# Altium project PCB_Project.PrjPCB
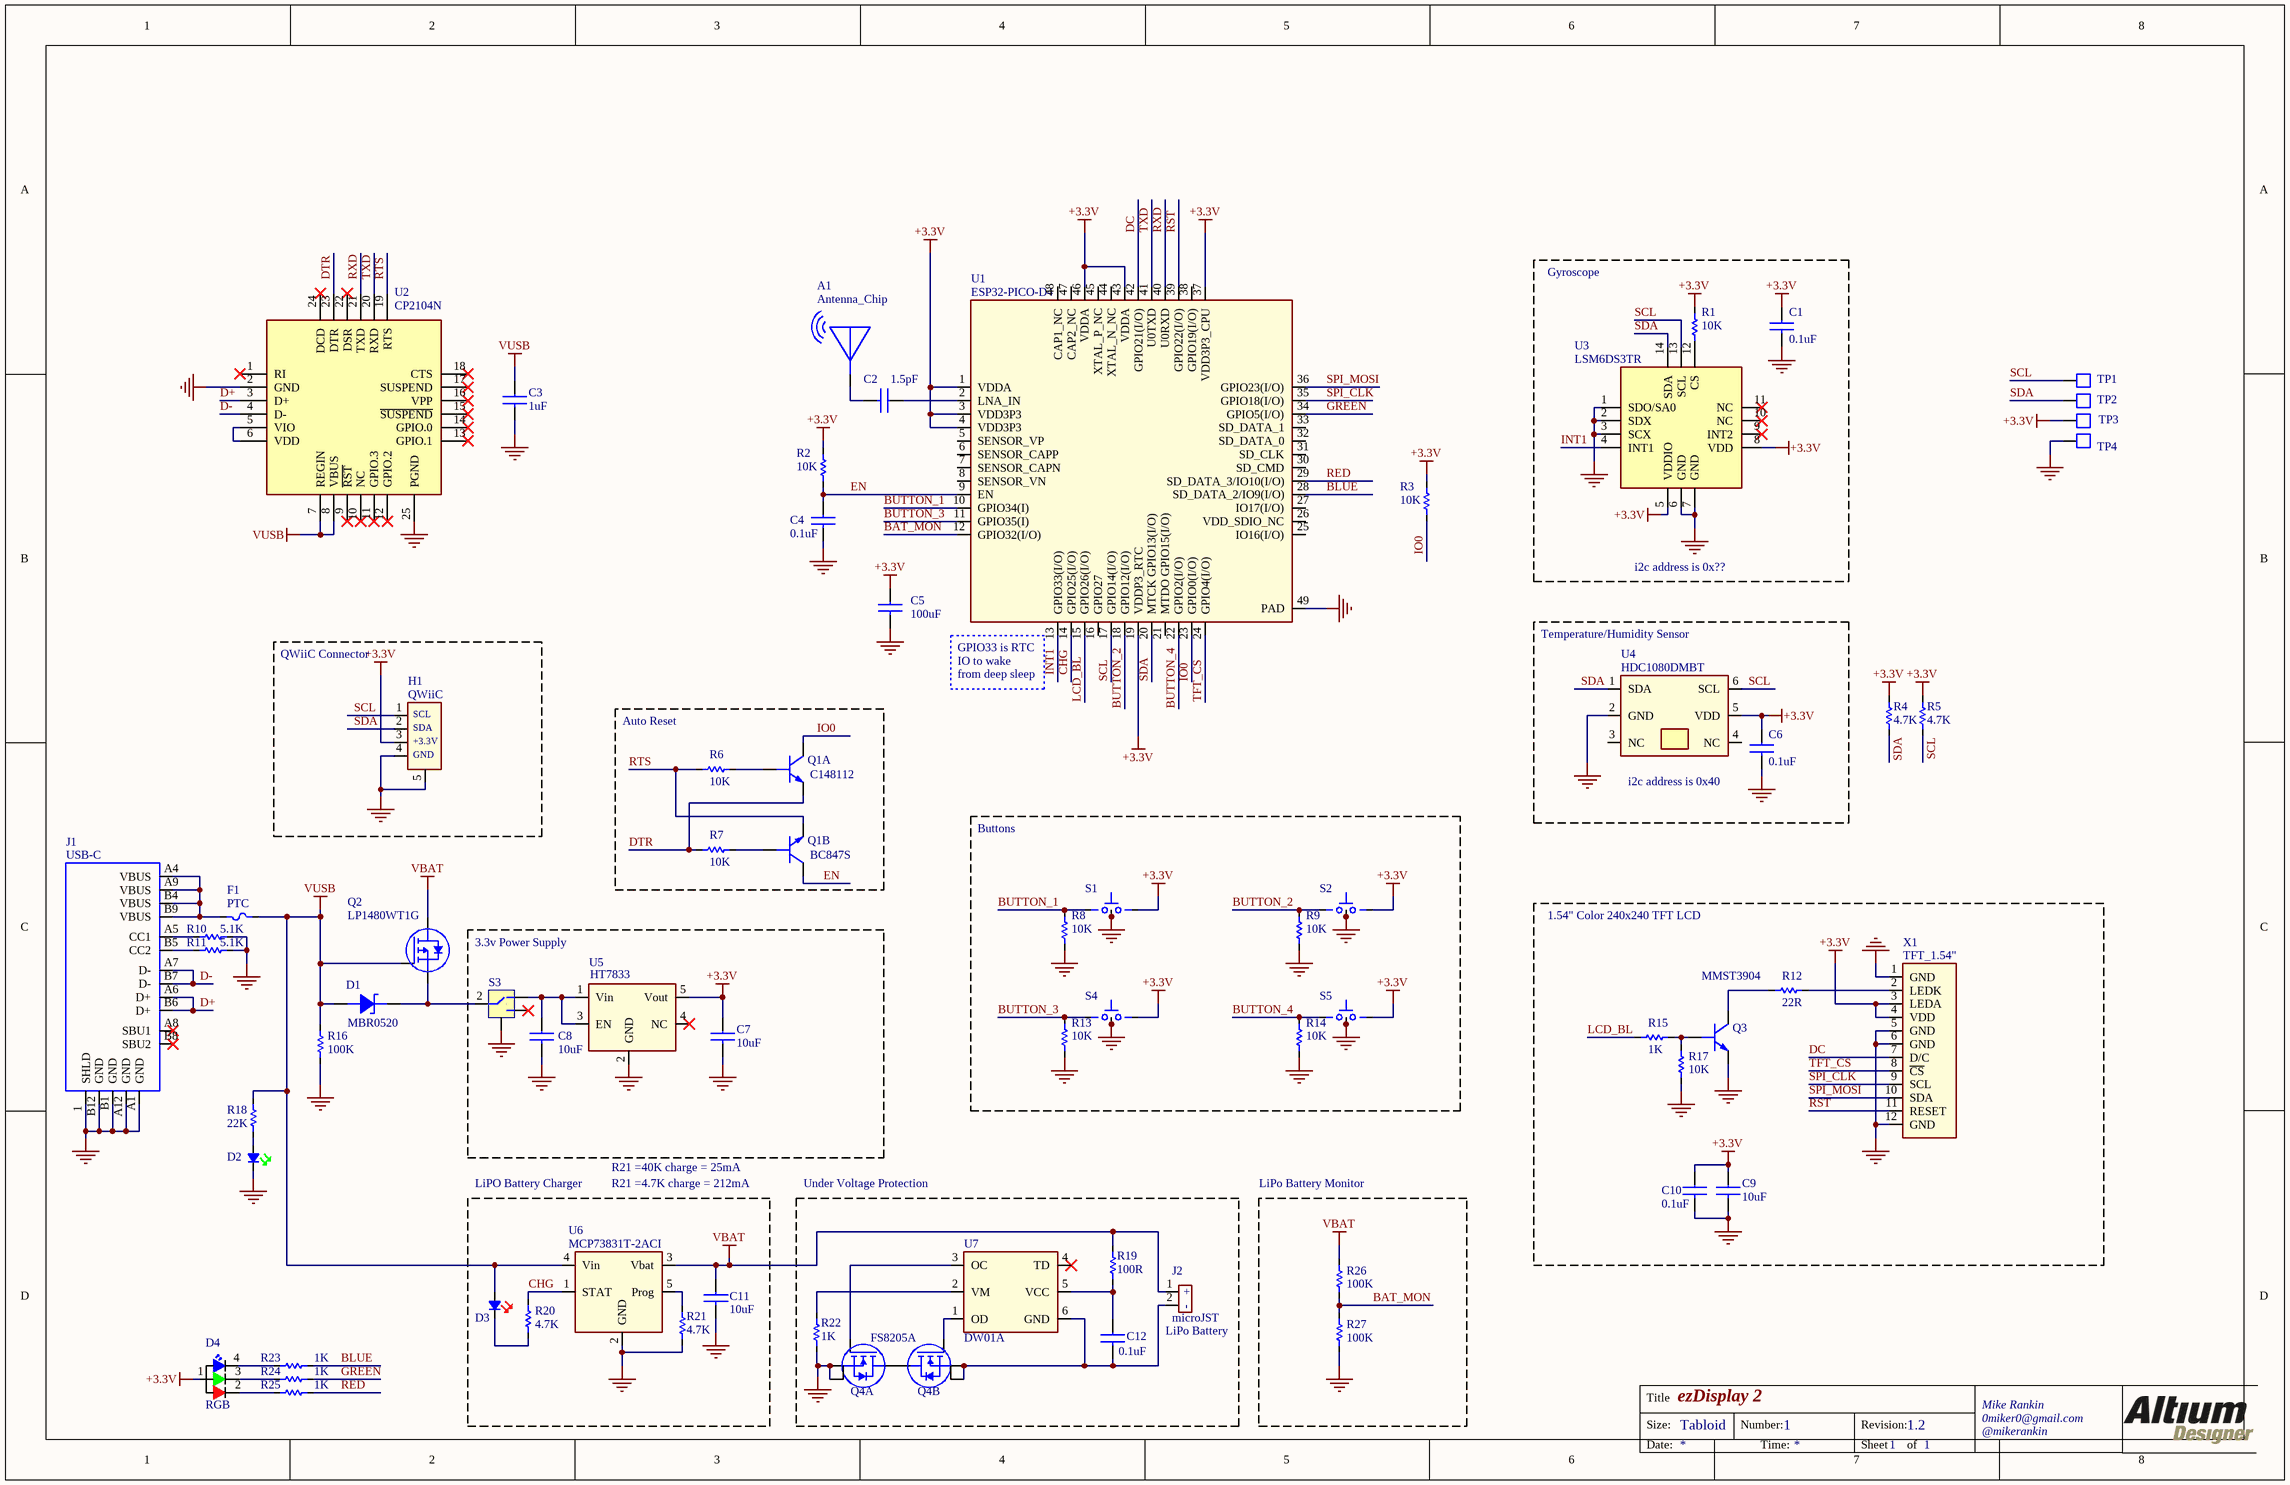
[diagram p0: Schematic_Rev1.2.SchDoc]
1 sheet, 69 parts. Net scope: global (net labels, ports and power ports of the same name join across sheets).
Board file: PCB_Rev1.2.PcbDoc

## Sheet Schematic_Rev1.2.SchDoc: ezDisplay 2
size Tabloid; DrawnBy: x; Engineer: x; Address1: Mike Rankin; Address2: 0miker0@gmail.com; Address3: @mikerankin; DocumentNumber: 1; Revision: 1.2; SheetNumber: 1; SheetTotal: 1

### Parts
A1  Antenna_Chip  [AN9520-245]
C1  0.1uF  [CAPC1005X56N]
C2  1.5pF  [CAPC1005X56N]
C3  1uF  [CAPC1005X56N]
C4  0.1uF  [CAPC1005X56N]
C5  100uF  [CAPC3216X160L]
C6  0.1uF  [CAPC1005X56N]
C7  10uF  [CAPC2012X140N]
C8  10uF  [CAPC2012X140N]
C9  10uF  [CAPC2012X140N]
C10  0.1uF  [CAPC1005X56N]
C11  10uF  [CAPC2012X140N]
C12  0.1uF  [CAPC1005X56N]
D1  MBR0520  [SOD123]
D2  Green Led  [LED1005X40N-Green]  (value not drawn)
D3  Red Led  [LED1005X40N-Red]  (value not drawn)
D4  RGB  [FC-B1010RGBT-HG]
F1  TLC-PSMD050  [PTC2012X70L]  (value not drawn)
H1  QWiiC  [SM04B-SRSS-TB]
J1  USB-C  [TYPE-C-31-M-12]
J2  CON2  [JST_Micro_2PIN]  (value not drawn)
Q1  LCSC_Part_Number: C148112  [SOT65P210X110-6N]  (hidden comment: BC847S)  (parts A,B of 2)
Q2  LP1480WT1G  [SC-70]
Q3  MMST3904  [SC-70]
Q4  FS8205A  [TSOP65P490X110-8N WIDE]  (value not drawn)  (parts A,B of 2)
R1  10K  [RESC1005X40L (0402 FOOTPRINT)]
R2  10K  [RESC1005X40L (0402 FOOTPRINT)]
R3  10K  [RESC1005X40L (0402 FOOTPRINT)]
R4  4.7K  [RESC1005X40L (0402 FOOTPRINT)]
R5  4.7K  [RESC1005X40L (0402 FOOTPRINT)]
R6  10K  [RESC1005X40L (0402 FOOTPRINT)]
R7  10K  [RESC1005X40L (0402 FOOTPRINT)]
R8  10K  [RESC1005X40L (0402 FOOTPRINT)]
R9  10K  [RESC1005X40L (0402 FOOTPRINT)]
R10  5.1K  [RESC1005X40L (0402 FOOTPRINT)]
R11  5.1K  [RESC1005X40L (0402 FOOTPRINT)]
R12  22R  [RESC1005X40L (0402 FOOTPRINT)]
R13  10K  [RESC1005X40L (0402 FOOTPRINT)]
R14  10K  [RESC1005X40L (0402 FOOTPRINT)]
R15  1K  [RESC1005X40L (0402 FOOTPRINT)]
R16  100K  [RESC1005X40L (0402 FOOTPRINT)]
R17  10K  [RESC1005X40L (0402 FOOTPRINT)]
R18  22K  [RESC1005X40L (0402 FOOTPRINT)]
R19  100R  [RESC1005X40L (0402 FOOTPRINT)]
R20  4.7K  [RESC1005X40L (0402 FOOTPRINT)]
R21  4.7K  [RESC1005X40L (0402 FOOTPRINT)]
R22  1K  [RESC1005X40L (0402 FOOTPRINT)]
R23  1K  [RESC1005X40L (0402 FOOTPRINT)]
R24  1K  [RESC1005X40L (0402 FOOTPRINT)]
R25  1K  [RESC1005X40L (0402 FOOTPRINT)]
R26  100K  [RESC1005X40L (0402 FOOTPRINT)]
R27  100K  [RESC1005X40L (0402 FOOTPRINT)]
S1  Push  [122514]  (value not drawn)
S2  Push  [122514]  (value not drawn)
S3  SWITCH SLIDE  [K3-1296S-E1]  (value not drawn)
S4  Push  [122514]  (value not drawn)
S5  Push  [122514]  (value not drawn)
TP1  Test Point, 1mm Top Layer  [TP100TL]  (value not drawn)  (no BOM)
TP2  Test Point, 1mm Top Layer  [TP100TL]  (value not drawn)  (no BOM)
TP3  Test Point, 1mm Top Layer  [TP100TL]  (value not drawn)  (no BOM)
TP4  Test Point, 1mm Top Layer  [TP100TL]  (value not drawn)  (no BOM)
U1  ESP32-PICO-D4  [QFN48_NEWEST 0.5mm pitch]
U2  CP2104N  [24-QFN]
U3  LSM6DS3TR  [LSM6DS3]
U4  HDC1080DMBT  [HDC1080]
U5  HT7833  [SOT95P280X144-5N]
U6  value MCP73831T-2ACI  [SOT95P280X144-5N]  (hidden comment: MCP73831T-2ACI/OT)
U7  DW01A  [SOT95P280X130-6N]
X1  TFT_1.54"  [TFT_GLASS 1.54 INCH]

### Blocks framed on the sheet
QWiiC Connector: H1
Auto Reset: Q1 R6 R7
Buttons: R8 R9 R13 R14 S1 S2 S4 S5
1.54" Color 240x240 TFT LCD: C9 C10 Q3 R12 R15 R17 X1
3.3v Power Supply: C7 C8 S3 U5
LiPo Battery Monitor: R26 R27

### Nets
+3.3V: C1.1 C5.1 C6.1 C7.1 C9.1 C10.1 D4.1 H1.3 R1.1 R2.1 R3.1 R4.2 R5.2 S1.2(B) S2.2(B) S4.2(B) S5.2(B) TP3.1 U1.1(VDDA) U1.3(VDD3P3) U1.4(VDD3P3) U1.19(VDDP3_RTC) U1.37(VDD3P3_CPU) U1.43(VDDA) U1.46(VDDA) U3.5(VDDIO) U3.8(VDD) U4.5(VDD) U5.5(Vout) X1.3(LEDA) X1.4(VDD)
GND: C1.2 C3.2 C4.2 C5.2 C6.2 C7.2 C8.2 C9.2 C10.2 C11.2 D2.1 H1.4 H1.5 J1.1(SHLD) J1.A1(GND) J1.A12(GND) J1.B1(GND) J1.B12(GND) Q3.2(E) Q4.2(S) Q4.3(S) R8.2 R9.2 R10.2 R11.2 R13.2 R14.2 R16.2 R17.2 R21.2 R22.1 R27.2 S1.3 S1.4 S2.3 S2.4 S3.4 S4.3 S4.4 S5.3 S5.4 TP4.1 U1.49(PAD) U2.2(GND) U2.25(PGND) U3.1(SDO/SA0) U3.2(SDX) U3.3(SCX) U3.6(GND) U3.7(GND) U4.2(GND) U5.2(GND) U6.2(GND) X1.1(GND) X1.5(GND) X1.6(GND) X1.12(GND)
VBAT: C11.1 J2.1 Q2.3(D) R19.2 R26.1 U6.3(Vbat)
VUSB: C3.1 D1.2(Annode) D3.2 F1.1 Q2.1(G) R16.1 R18.2 U2.7(REGIN) U2.8(VBUS) U6.4(Vin)
BAT_MON: R26.2 R27.1 U1.12(GPIO32(I/O))
BLUE: R23.2 U1.28(SD_DATA_2/IO9(I/O))
BUTTON_1: R8.1 S1.1(A) U1.10(GPIO34(I))
BUTTON_2: R9.1 S2.1(A) U1.18(GPIO12(I/O))
BUTTON_3: R13.1 S4.1(A) U1.11(GPIO35(I))
BUTTON_4: R14.1 S5.1(A) U1.22(GPIO2(I/O))
CHG: R20.2 U1.14(GPIO25(I/O)) U6.1(STAT)
D+: J1.A6(D+) J1.B6(D+) U2.3(D+)
D-: J1.A7(D-) J1.B7(D-) U2.4(D-)
DC: U1.42(GPIO21(I/O)) X1.7(D/C)
DTR: Q1.1(E1) R7.2 U2.23(DTR)
EN: C4.1 Q1.3(C2) R2.2 U1.9(EN)
GREEN: R24.2 U1.34(GPIO5(I/O))
INT1: U1.13(GPIO33(I/O)) U3.4(INT1)
IO0: Q1.6(C1) R3.2 U1.23(GPIO0(I/O))
LCD_BL: R15.1 U1.15(GPIO26(I/O))
RED: R25.2 U1.29(SD_DATA_3/IO10(I/O))
RST: U1.39(GPIO22(I/O)) X1.11(RESET)
RTS: Q1.4(E2) R6.2 U2.19(RTS)
RXD: U1.40(U0RXD) U2.21(TXD)
SCL: H1.1 R5.1 TP1.1 U1.17(GPIO14(I/O)) U3.13(SCL) U4.6(SCL)
SDA: H1.2 R4.1 TP2.1 U1.20(MTCK_GPIO13(I/O)) U3.14(SDA) U4.1(SDA)
SPI_CLK: U1.35(GPIO18(I/O)) X1.9(SCL)
SPI_MOSI: U1.36(GPIO23(I/O)) X1.10(SDA)
TFT_CS: U1.24(GPIO4(I/O)) X1.8(~{CS})
TXD: U1.41(U0TXD) U2.20(RXD)
NetA1_1: A1.1 C2.2
NetC2_1: C2.1 U1.2(LNA_IN)
NetC8_1: C8.1 S3.1 U5.1(Vin) U5.3(EN)
NetC12_1: C12.1 R19.1 U7.5(VCC)
NetC12_2: C12.2 J2.2 Q4.6(S) Q4.7(S) U7.6(GND)
NetD1_1: D1.1(Cathode) Q2.2(S) S3.2
NetD2_2: D2.2 R18.1
NetD3_1: D3.1 R20.1
NetD4_2: D4.2 R25.1
NetD4_3: D4.3 R24.1
NetD4_4: D4.4 R23.1
NetF1_2: F1.2 J1.A4(VBUS) J1.A9(VBUS) J1.B4(VBUS) J1.B9(VBUS)
NetJ1_A5: J1.A5(CC1) R10.1
NetJ1_B5: J1.B5(CC2) R11.1
NetQ1_2: Q1.2(B1) R6.1
NetQ1_5: Q1.5(B2) R7.1
NetQ3_1: Q3.1(B) R15.2 R17.1
NetQ3_3: Q3.3(C) R12.2
NetQ4_1: Q4.1(D) Q4.8(D)
NetQ4_4: Q4.4(G) U7.3(OC)
NetQ4_5: Q4.5(G) U7.1(OD)
NetR1_2: R1.2 U3.12(CS)
NetR12_1: R12.1 X1.2(LEDK)
NetR21_1: R21.1 U6.5(Prog)
NetR22_2: R22.2 U7.2(VM)
NetU2_5: U2.5(VIO) U2.6(VDD)

Not connected (* = marked no-connect by the designer): J1 A8(SBU1)* B8(SBU2)*; S3 3*; U1 5(SENSOR_VP) 6(SENSOR_CAPP) 7(SENSOR_CAPN) 8(SENSOR_VN) 16(GPIO27) 21(MTDO_GPIO15(I/O)) 25(IO16(I/O)) 26(VDD_SDIO_NC) 27(IO17(I/O)) 30(SD_CMD) 31(SD_CLK) 32(SD_DATA_0) 33(SD_DATA_1) 38(GPIO19(I/O)) 44(XTAL_N_NC) 45(XTAL_P_NC) 47(CAP2_NC) 48(CAP1_NC); U2 1(RI)* 9(~{RST})* 10(NC)* 11(GPIO.3)* 12(GPIO.2)* 13(GPIO.1)* 14(GPIO.0)* 15(~{SUSPEND})* 16(VPP)* 17(SUSPEND)* 18(CTS)* 22(DSR)* 24(DCD)*; U3 9(INT2)* 10(NC)* 11(NC)*; U4 3(NC) 4(NC); U5 4(NC)*; U7 4(TD)*

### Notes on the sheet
- Gyroscope
- i2c address is 0x??
- (near U1) GPIO33 is RTC
- (near U1) IO to wake
- (near U1) from deep sleep
- (near U4) Temperature/Humidity Sensor
- i2c address is 0x40
- (near F1) PTC
- R21 =40K charge = 25mA
- LiPO Battery Charger
- R21 =4.7K charge = 212mA
- Under Voltage Protection
- (near J2) LiPo Battery
- (near J2) microJST

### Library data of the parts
A1 = Antenna_Chip: Antenna Chip 2.4Gig; Manufacturer: Rainsun; Value: Chip Antenna; Vendor: LCSC
C1 C4 C6 C10 C12 = CAP_0402: CAP 0.1uF 0402; Manufacturer: CCTC; Man_Part_Number: TCC0402X5R104M160AT; Vendor: LCSC
C2 = CAP_0402: CAP 1.5pF 0402; Manufacturer: Dafron; Part_Footprint: 0402; Man_Part_Number: C1005NP0159CGTS; Vendor: LCSC
C3 = CAP_0603: CAP 1uF 16V 0402; Manufacturer: Walsin; Man_Part_Number: 0402X105K160CT; Vendor: LCSC
C5 = CAP_1206: CAP 100uF 6.3V 1206; Manufacturer: Taiyo Yuden; Man_Part_Number: JMK316BJ107ML-T; Vendor: LCSC
C7-C9 C11 = CAP_0805: CAP 10uF 0805; Manufacturer: Samsung; Man_Part_Number: CL21A106KOQNNNG; Vendor: LCSC
D1 = MBR0520-TP: DIODE SCHOTTKY 20V 500MA SOD123; Manufacturer: CJ; Vendor: LCSC
D2 = LED_0402_SMALL_GREEN: LED Green 0402; Manufacturer: Lite-On; Part_Footprint: 0402; Man_Part_Number: 16-213/GHC-YR1S1/3T; Vendor: LCSC
D3 = LED_0402_SMALL_Red: LED RED 0402; Manufacturer: Lite-On; Part_Footprint: 0402; Man_Part_Number: LTST-C281KRKT; Vendor: LCSC
D4 = FC-B1010RGBT-HG: LED,RGB LED,SMD,RoHS; Manufacturer: Foshan; Vendor: LCSC; Value: RGB Led
F1 = PTC_FUSE: PTC FUSE 500mA hold, 1A trip 0805 SMD; Manufacturer: TLC; Vendor: LCSC
H1 = SM04B-SRSS-TB: CONN HEADER 4POS .100 R/A QWIIC; Manufacturer: JST; PartNumber: SM04B-SRSS-TB(LF)(SN); Vendor: LCSC
J1 = USB-C: CONN RECPT USB-C; Manufacturer: KHE; Part_Footprint: SMT; Vendor: LCSC
J2 = JST_Micro_CONN_2PIN: MIcro CONN 2POS 1.0MM SMT R/A; Manufacturer: JUSHUO; Man_Part_Number: AFC10-S02QCC-00; Vendor: LCSC; Value: Batt Con
Q1 = BC847S: TRANS 2NPN 44V 0.1A SC-70-6; Manufacturer: Changjiang; Vendor: LCSC
Q2 = LP1480WT1G: MOSFET P-CH 20V 1.4A SC-70; Manufacturer: LRC; Vendor: LCSC; Value: P-CH Mosfet
Q3 = MMST3904: TRANSISTOR NPN GP 40V SC-70; Manufacturer: Changjiang; Vendor: LCSC
Q4 = FS8205A: MOSFET 2N-CH 20V 6A TSSOP-8L; Manufacturer: Fortune; Vendor: LCSC
R1-R3 R6 R7 R17 = RES_0402: RES 10K 0402; Manufacturer: Guangdong; Man_Part_Number: RC-02W1002FT; Vendor: LCSC
R4 R5 = RES_0402: RES 4.7K 0402; Manufacturer: Uni-Royal; Man_Part_Number: 0402WGF4701TCE; Vendor: LCSC
R8 R9 R13 R14 = RES_0402: RES 10K 0402; Manufacturer: Guangdong; Part_Footprint: 0402; Man_Part_Number: RC-02W1002FT; Vendor: LCSC
R10 R11 = RES_0603: RES 5.1K 0402; Manufacturer: TyoHM; Man_Part_Number: RMC04025.1K1%N; Vendor: LCSC
R12 = RES_0402: RES 22R 0402; Manufacturer: Uniroyal; Man_Part_Number: 0402WGF220JTCE; Vendor: LCSC
R15 R22-R25 = RES_0402: RES 1K 0402; Manufacturer: Yageo; Man_Part_Number: RC0402FR-071KL; Vendor: LCSC
R16 R26 R27 = RES_0603: RES 100K 0402; Manufacturer: Uniroyal Elec; Man_Part_Number: 0402WGF1003TCE; Vendor: LCSC
R18 = RES_0603: RES 22K 0402; Manufacturer: LIZ Elec; Man_Part_Number: CR0402FF2202G; Vendor: LCSC
R19 = RES_0603: RES 100R 0402; Manufacturer: Yageo; Man_Part_Number: RC0402FR-07100RL; Vendor: LCSC
R20 R21 = RES_0603: RES 4.7K 0402; Manufacturer: Uni-Royal; Man_Part_Number: 0402WGF4701TCE; Vendor: LCSC
S1 S2 S4 S5 = Side Actuated Button R/A: Manufacturer: HYP; Man_Part_Number: 1TS002G-2300-3500-CT; Vendor: LCSC
S3 = K3-1296S-E1: SWITCH SLIDE SMD; Manufacturer: Korean Hroparts Elec; Vendor: LCSC
U1 = ESP32-PICO-D4: RF Transceiver ICs QFN-48_7x7x05P RoHS; Manufacturer: Espressif; Part_Footprint: QFN-48; Vendor: LCSC
U2 = CP2104N: IC BRIDGE USB TO UART 24QFN; Manufacturer: Silicon Labs; Man_Part_Number: CP2104-F03-GMR; Vendor: LCSC
U3 = LSM6DS3 (obsolete): IMU ACCEL/GYRO I2C/SPI 14VFLGA; Manufacturer: ST MICRO; Vendor: LCSC
U4 = HDC1080DMBT: Humidity/Temperature Sensor; Manufacturer: Texas Instruments; Man_Part_Number: HDC1080DMBR; Vendor: LCSC
U5 = HT7833: IC LDO 3.3V 0.5A SOT23-5; Manufacturer: Holtek; Part_Footprint: SOT-23-5L; Vendor: LCSC
U6 = MCP73831T-2ACI/OT: Charger IC Lithium-Ion/Polymer SOT23-5; Manufacturer: Microchip; Part_Footprint: SOT-23-5L; Vendor: LCSC
U7 = DW01A: IC LITHIUM BATT PROTECT SOT-23-6L; Manufacturer: PUOLOP; Vendor: LCSC
X1 = TFT_GLASS 1.54 INCH COLOR: 1.54 INCH TFT GLASS COLOR; Man_Part_Number: ER-TFT1.54-1; Manufacturer: BuyDisplay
